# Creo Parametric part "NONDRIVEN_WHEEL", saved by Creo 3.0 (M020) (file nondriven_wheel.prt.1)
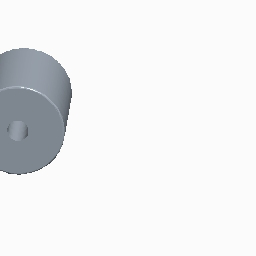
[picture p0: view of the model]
Units: millimeter Newton Second (mmNs); MM, TONNE, SECS

Created from: MMNS_PART_SOLID.PRT

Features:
  1. datum plane "RIGHT"
  2. datum plane "TOP"
  3. datum plane "FRONT"
  4. coordinate system
  5. sketch "Sketch 1"
  6. extrusion "Extrude 1"
  7. round "Round 1"

Surfaces: 5 plane, 4 cylinder, 4 torus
